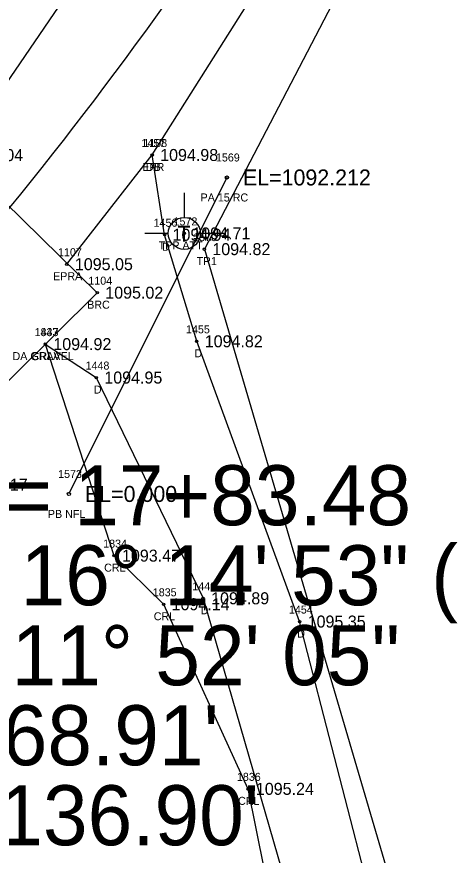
# Model space of a CAD drawing. Extents: x 1539151 to 1541799, y 1198646 to 1201165.
# Drawn here: x 1540164.3 to 1540218.7, y 1199420.8 to 1199525.6 of the extents above; entities that cross this region are included whole.
import ezdxf

# ---------------------------------------------------------------- set-up
doc = ezdxf.new("R2010")
doc.units = 0
for name, color, linetype in [('RD_EX_Bridge', 7, 'Continuous'), ('RD_EX_Bridge_txCode', 7, 'Continuous'), ('RD_EX_DR_Pipe', 7, 'Continuous'), ('RD_EX_DR_Pipe_txCode', 7, 'Continuous'), ('RD_EX_Driveway', 7, 'Continuous'), ('RD_EX_Driveway_txCode', 7, 'Continuous'), ('RD_EX_H2O', 7, 'Continuous'), ('RD_EX_H2O_txCode', 7, 'Continuous'), ('RD_EX_Road', 7, 'Continuous'), ('RD_EX_Road_txCode', 7, 'Continuous'), ('RD_EX_TX_Bridge_ELEV', 7, 'Continuous'), ('RD_EX_TX_Driveway_ELEV', 7, 'Continuous'), ('RD_EX_TX_H2O_ELEV', 7, 'Continuous'), ('RD_EX_TX_Road_ELEV', 7, 'Continuous'), ('RD_EX_TX_UT_ELEV', 7, 'Continuous'), ('RD_EX_TX_VEG_ELEV', 7, 'Continuous'), ('RD_EX_UT', 7, 'Continuous'), ('RD_EX_UT_txCode', 7, 'Continuous'), ('RD_EX_VEG', 7, 'Continuous'), ('RD_EX_VEG_txCode', 7, 'Continuous'), ('RD_HC_Cl', 7, 'Continuous'), ('RD_HC_Data', 7, 'Continuous'), ('RD_SMD_Locator', 7, 'Continuous'), ('RD_TX_Pipe_ElevEX', 7, 'Continuous')]:
    doc.layers.add(name, color=color, linetype=linetype)

msp = doc.modelspace()

# ---------------------------------------------------------------- linework, layer by layer
at = {"layer": 'RD_EX_Bridge'}
msp.add_lwpolyline([(1540110.32, 1199427.56), (1540091.92, 1199445.97), (1540155.71, 1199509.35), (1540174.37, 1199491.07), (1540110.32, 1199427.56)], dxfattribs=at)
at = {"layer": 'RD_EX_DR_Pipe'}
msp.add_line((1540190.57, 1199505.47), (1540170.83, 1199465.91), dxfattribs=at)
at = {"layer": 'RD_EX_Driveway'}
for points in [[(1540214.21, 1199379.03), (1540209.04, 1199413.48), (1540199.66, 1199449.96), (1540186.8, 1199484.99), (1540182.78, 1199498.31), (1540181.23, 1199508.28)], [(1540167.88, 1199484.64), (1540174.25, 1199480.46), (1540187.6, 1199452.87), (1540197.92, 1199417.13), (1540203.64, 1199379.48)]]:
    msp.add_lwpolyline(points, dxfattribs=at)
at = {"layer": 'RD_EX_H2O'}
msp.add_lwpolyline([(1540167.88, 1199484.64), (1540176.46, 1199458.2), (1540182.66, 1199452.12), (1540193.19, 1199429.05), (1540200.37, 1199393.5), (1540202.4, 1199340.71), (1540198.55, 1199306.73), (1540179.64, 1199280.12), (1540151.78, 1199264.65), (1540144.74, 1199262.14), (1540137.88, 1199248.47), (1540155.53, 1199232.49), (1540156.47, 1199194.6), (1540144.81, 1199166.15), (1540127.69, 1199133.28), (1540119.65, 1199099.79), (1540112.02, 1199051.08), (1540113.69, 1199004.24), (1540113.12, 1198937.28), (1540119.39, 1198871.63)], dxfattribs=at)
at = {"layer": 'RD_EX_Road'}
for points in [[(1540156.86, 1199508.27), (1540186.51, 1199551.73), (1540214.32, 1199591.31), (1540249.72, 1199632.22), (1540286.8, 1199666.61), (1540324.36, 1199693.31), (1540344.92, 1199710.43), (1540367.33, 1199727.77), (1540402.7, 1199760.37), (1540437.37, 1199795.58), (1540455.74, 1199815.52), (1540466.15, 1199827.23), (1540503.86, 1199868.5), (1540538.69, 1199906.78), (1540571.44, 1199944.18), (1540603.42, 1199982.61), (1540638.15, 1200019.15), (1540672.1, 1200056.68), (1540705.32, 1200094.04), (1540739.01, 1200131.56)], [(1540170.57, 1199494.63), (1540181.23, 1199508.28), (1540202.24, 1199541.54), (1540230.14, 1199581.95), (1540262.76, 1199618.79), (1540299.65, 1199650.78), (1540338.78, 1199681.63), (1540378.45, 1199712.68), (1540416.67, 1199747.15), (1540451.68, 1199783.64), (1540485.11, 1199820.19), (1540518.57, 1199856.95), (1540552.63, 1199894.89), (1540585.47, 1199932.32), (1540619.12, 1199969.78), (1540652.74, 1200007.33), (1540685.87, 1200044.5), (1540718.68, 1200081.33), (1540762.24, 1200130.19)]]:
    msp.add_lwpolyline(points, dxfattribs=at)
at = {"layer": 'RD_EX_UT'}
for p, q in [((1540185.25, 1199503.55), (1540185.25, 1199500.48)), ((1540180.32, 1199498.49), (1540183.25, 1199498.49)), ((1540187.25, 1199498.49), (1540190.32, 1199498.49))]:
    msp.add_line(p, q, dxfattribs=at)
msp.add_circle((1540185.25, 1199498.48), 2, dxfattribs=at)
at = {"layer": 'RD_EX_VEG'}
msp.add_lwpolyline([(1540836.37, 1200082.45), (1540794.45, 1200101.71), (1540758.65, 1200106.39), (1540697.29, 1200033.83), (1540560.39, 1199886.45), (1540422.51, 1199739.87), (1540382.08, 1199704.72), (1540267.52, 1199610.92), (1540233.68, 1199579.65), (1540209.33, 1199537.96), (1540187.75, 1199496.51), (1540221.64, 1199381.22)], dxfattribs=at)
at = {"layer": 'RD_HC_Cl'}
msp.add_arc((1539789.52, 1199807.08), 482.77, 309.3443, 325.5923, dxfattribs=at)
at = {"layer": 'RD_SMD_Locator'}
for centre, radius in [((1540181.23, 1199508.28), 0.15), ((1540181.23, 1199508.28), 0.15), ((1540190.57, 1199505.47), 0.2), ((1540182.78, 1199498.31), 0.15), ((1540185.25, 1199498.48), 0.15), ((1540187.75, 1199496.51), 0.15), ((1540170.57, 1199494.63), 0.15), ((1540174.37, 1199491.07), 0.15), ((1540186.8, 1199484.99), 0.15), ((1540167.88, 1199484.64), 0.15), ((1540167.88, 1199484.64), 0.15), ((1540174.25, 1199480.46), 0.15), ((1540170.83, 1199465.91), 0.2), ((1540176.46, 1199458.2), 0.15), ((1540187.6, 1199452.87), 0.15), ((1540182.66, 1199452.12), 0.15), ((1540199.66, 1199449.96), 0.15), ((1540193.19, 1199429.05), 0.15)]:
    msp.add_circle(centre, radius, dxfattribs=at)

# ---------------------------------------------------------------- texts
at = {"layer": 'RD_EX_Bridge_txCode'}
for s, p in [('1104', (1540173.26, 1199492.07)), ('BRC', (1540173.11, 1199489.07))]:
    msp.add_text(s, height=1, dxfattribs=at).set_placement(p)
at = {"layer": 'RD_EX_DR_Pipe_txCode'}
for s, p in [('1569', (1540189.2, 1199507.47)), ('PA 15 RC', (1540187.28, 1199502.47)), ('1573', (1540169.48, 1199467.91)), ('PB NFL', (1540168.2, 1199462.91))]:
    msp.add_text(s, height=1, dxfattribs=at).set_placement(p)
at = {"layer": 'RD_EX_Driveway_txCode'}
for s, p in [('1457', (1540179.89, 1199509.28)), ('DB', (1540180.45, 1199506.28)), ('1456', (1540181.41, 1199499.31)), ('D', (1540182.47, 1199496.31)), ('1447', (1540166.54, 1199485.64)), ('1455', (1540185.46, 1199485.99)), ('DA GRAVEL', (1540163.78, 1199482.64)), ('D', (1540186.5, 1199482.99)), ('1448', (1540172.91, 1199481.46)), ('D', (1540173.94, 1199478.46)), ('1449', (1540186.25, 1199453.87)), ('D', (1540187.29, 1199450.87)), ('1454', (1540198.32, 1199450.96)), ('D', (1540199.36, 1199447.96))]:
    msp.add_text(s, height=1, dxfattribs=at).set_placement(p)
at = {"layer": 'RD_EX_H2O_txCode'}
for s, p in [('1833', (1540166.54, 1199485.64)), ('CRLA', (1540166.17, 1199482.64)), ('1834', (1540175.11, 1199459.2)), ('CRL', (1540175.23, 1199456.2)), ('1835', (1540181.31, 1199453.12)), ('CRL', (1540181.43, 1199450.12)), ('1836', (1540191.82, 1199430.05)), ('CRL', (1540191.97, 1199427.05))]:
    msp.add_text(s, height=1, dxfattribs=at).set_placement(p)
at = {"layer": 'RD_EX_Road_txCode'}
for s, p in [('1108', (1540180.13, 1199509.28)), ('EPR', (1540180, 1199506.28)), ('1107', (1540169.47, 1199495.63)), ('EPRA', (1540168.85, 1199492.63))]:
    msp.add_text(s, height=1, dxfattribs=at).set_placement(p)
at = {"layer": 'RD_EX_TX_Bridge_ELEV'}
msp.add_text('1095.02', height=1.5, dxfattribs=at).set_placement((1540175.37, 1199490.32))
at = {"layer": 'RD_EX_TX_Driveway_ELEV'}
for s, p in [('1094.98', (1540182.23, 1199507.53)), ('1094.94', (1540183.78, 1199497.56)), ('1094.92', (1540168.88, 1199483.89)), ('1094.82', (1540187.8, 1199484.24)), ('1094.95', (1540175.25, 1199479.71)), ('1094.89', (1540188.6, 1199452.12)), ('1095.35', (1540200.66, 1199449.21))]:
    msp.add_text(s, height=1.5, dxfattribs=at).set_placement(p)
at = {"layer": 'RD_EX_TX_H2O_ELEV'}
for s, p in [('1094.92', (1540168.88, 1199483.89)), ('EL=1081.017', (1540153.68, 1199466.32)), ('1093.47', (1540177.46, 1199457.45)), ('1094.14', (1540183.66, 1199451.37)), ('1095.24', (1540194.19, 1199428.3))]:
    msp.add_text(s, height=1.5, dxfattribs=at).set_placement(p)
at = {"layer": 'RD_EX_TX_Road_ELEV'}
for s, p in [('1095.04', (1540157.86, 1199507.52)), ('1094.98', (1540182.23, 1199507.53)), ('1095.05', (1540171.57, 1199493.88))]:
    msp.add_text(s, height=1.5, dxfattribs=at).set_placement(p)
at = {"layer": 'RD_EX_TX_UT_ELEV'}
msp.add_text('1094.71', height=1.5, dxfattribs=at).set_placement((1540186.25, 1199497.73))
at = {"layer": 'RD_EX_TX_VEG_ELEV'}
msp.add_text('1094.82', height=1.5, dxfattribs=at).set_placement((1540188.75, 1199495.76))
at = {"layer": 'RD_EX_UT'}
msp.add_text('T', height=2, dxfattribs=at).set_placement((1540184.4, 1199497.43))
at = {"layer": 'RD_EX_UT_txCode'}
for s, p in [('1572', (1540183.9, 1199499.48)), ('TPP ATT', (1540182.04, 1199496.48))]:
    msp.add_text(s, height=1, dxfattribs=at).set_placement(p)
at = {"layer": 'RD_EX_VEG_txCode'}
for s, p in [('1570', (1540186.36, 1199497.51)), ('TR1', (1540186.79, 1199494.51))]:
    msp.add_text(s, height=1, dxfattribs=at).set_placement(p)
at = {"layer": 'RD_HC_Data'}
for s, p in [('P.I. = 17+83.48', (1540145, 1199462)), ('    = 16%%d 14\' 53" (LT)', (1540145, 1199452)), ('D = 11%%d 52\' 05"', (1540145, 1199442)), ("T = 68.91'", (1540145, 1199432)), ("L = 136.90'", (1540145, 1199422))]:
    msp.add_text(s, height=7.5, dxfattribs=at).set_placement(p)
at = {"layer": 'RD_TX_Pipe_ElevEX'}
for s, p in [('EL=1092.212', (1540192.57, 1199504.47)), ('EL=0.000', (1540172.83, 1199464.91))]:
    msp.add_text(s, height=2, dxfattribs=at).set_placement(p)

doc.saveas('drawing.dxf')
